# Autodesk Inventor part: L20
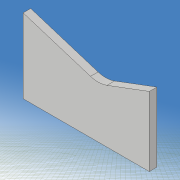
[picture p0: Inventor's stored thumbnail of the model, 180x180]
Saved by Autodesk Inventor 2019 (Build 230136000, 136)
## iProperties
Created: 2021-05
Part Number: L20
Material: 一般
Document SubType Name: Modeling
Designer: kikut
Density: 1 g/cm^3
Appearance: 既定
Mass: 0.00934248 g
Surface Area: 0.426451 cm^2
Volume: 0.00934248 cm^3
Author: kikut
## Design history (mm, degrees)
sketch "スケッチ1"
  geometry: L1 (80, 60)-(-80, 60); L2 (-80, 60)-(-80, -60); L3 (-80, -60)-(80, -60); L4 (80, -60)-(80, 60); L5 (80, 60)-(-80, -60); L6 (-80, 60)-(80, -60); 1 further point
  constraints: 12 end point, 2 midpoint, 2 parallel, 1 horizontal, 1 perpendicular
  dimensions: "d0" = 160 distance of L2.end L3.end; "d1" = 120 distance of L1.end L2.end
extrude "押し出し1" new body sketch "スケッチ1" stored distance "d2" = 0.6; taper "d3" = 0 deg
sketch "スケッチ2"
  geometry: L1 (-140, 0)-(140, 0) reference; L2 (0, -54)-(20, -30); L3 (0, 54)-(20, 30); L4 (0, -3)-(6.514, -3); L5 (6.514, -3)-(16, -6); L6 (16, -6)-(24, -3); L7 (24, -3)-(33.716, -3); L8 (0, 3)-(6.514, 3); L9 (6.514, 3)-(16, 6); L10 (16, 6)-(24, 3); L11 (24, 3)-(33.716, 3); L12 (0, -98)-(0, 98) reference; L13 (-100, -70)-(100, -70); L14 (100, -70)-(100, 70); L15 (100, 70)-(-100, 70); L16 (-100, 70)-(-100, -70); L17 (-100, -70)-(100, 70); L18 (100, -70)-(-100, 70); A1 r 60 centre (54.312, 28.5) between (0, 54) and (0, 3); A2 r 60 centre (54.312, -28.5) between (0, -3) and (0, -54); A3 r 18.111 centre (18, -12) between (20, -30) and (33.716, -3); A4 r 18.111 centre (18, 12) between (33.716, 3) and (20, 30); 1 further point
  constraints: 32 end point, 8 point on circle, 8 symmetric about line, 4 centre point, 3 horizontal, 2 collinear, 2 midpoint, 2 parallel, 1 perpendicular
  dimensions: "d5" = 60 radius of A1; "d6" = 6 distance of L8.start L4.start; "d7" = 108 distance of L3.start L2.start; "d8" = 0 horizontal distance of L3.start L8.start; "d9" = 60 distance of L3.end L2.end; "d10" = 0 horizontal distance of point (0, 0) L3.start; "d11" = 20 horizontal distance of L3.start L3.end; "d12" = 24 distance of A4.centre A3.centre; "d13" = 6 distance of L11.end L7.end; "d14" = 12 distance of L9.end L5.end; "d15" = 16 distance from line of L12 L5.end; "d16" = 24 distance from line of L6.end L12; "d17" = 200 distance of L14.end L15.end; "d18" = 140 distance of L15.end L13.start; "d30" = 18 distance from line of L12 A4.centre
extrude "押し出し2" cut sketch "スケッチ2" stored distance "d19" = 10; taper "d20" = 0 deg
sketch "スケッチ3"
  geometry: L1 (49.705, -17.97)-(33.948, -15.191); L2 (33.948, -15.191)-(34.295, -13.222); L3 (34.295, -13.222)-(50.052, -16); L4 (50.052, -16)-(49.705, -17.97); L5 (49.705, -17.97)-(34.295, -13.222); L6 (33.948, -15.191)-(50.052, -16); L7 (50.052, 16)-(34.295, 13.222); L8 (34.295, 13.222)-(33.948, 15.191); L9 (33.948, 15.191)-(49.705, 17.97); L10 (49.705, 17.97)-(50.052, 16); L11 (50.052, 16)-(33.948, 15.191); L12 (34.295, 13.222)-(49.705, 17.97); L13 (-112, 0)-(112, 0) reference; L14 (0, -84)-(0, 84) reference; 3 further points
  constraints: 24 end point, 4 midpoint, 4 parallel, 2 perpendicular, 2 symmetric about line
  dimensions: "d21" = 2 distance of L3.end L1.start; "d22" = 2 distance of L9.end L7.start; "d23" = 16 distance of L8.end L9.end; "d24" = 42 distance from line of L14 point (42, 15.596); "d26" = 10 deg angle of L7 L13; "d62" = 16 distance from line of L3.end L13
extrude "押し出し3" join sketch "スケッチ3" distance "d27" = 0.6; taper "d28" = 0 deg
fillet "フィレット1" dims "d31" = 2
fillet "フィレット2" dims "d32" = 1
sketch "スケッチ7"
  geometry: L1 (-20, 60)-(80, 60); L2 (80, 60)-(80, -60); L3 (80, -60)-(-20, -60); L4 (-20, -60)-(-20, 60); L5 (0, -82.207)-(0, 85.793) reference; L6 (-40, 0)-(100, 0) reference; L7 (10, 0)-(20, 0); L8 (20, 0)-(20, -10); L9 (20, -10)-(10, -10); L10 (10, -10)-(10, 0); 1 further point
  constraints: 16 end point, 4 parallel, 2 horizontal, 2 perpendicular, 1 other
  dimensions: "d80" = 120 distance of L3.end L1.start; "d81" = 20 distance between parallel lines of L5 L4; "d82" = 100 distance of L1.start L1.end; "d84" = 10 distance of L8.end L9.end; "d85" = 10 distance of L7.end L8.end; "d86" = 30 distance between parallel lines of L4 L10; "d90" = 0 distance between parallel lines of L7 L6
extrude "押し出し5" cut sketch "スケッチ7" stored distance "d87" = 10; taper "d88" = 0 deg
node "ソリッド1"
